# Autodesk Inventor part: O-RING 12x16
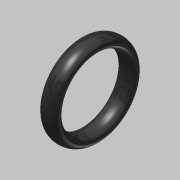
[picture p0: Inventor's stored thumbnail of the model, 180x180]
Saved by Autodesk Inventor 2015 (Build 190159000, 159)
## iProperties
Created: 2020-02
Part Number: O-RING 12x16
Material: 고무
Document SubType Name: Modeling
Designer: mduedu
Density: 1 g/cm^3
Appearance: 고무 - 검은색 - 버전 1.1
Author: mduedu
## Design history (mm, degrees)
sketch "스케치1"
  geometry: L1 (-2.24, 0)-(2.24, 0) reference; L2 (-1.6, 7)-(1.6, 7); L3 (0, 8)-(0, 6); 6 further points; 1 other entity
  constraints: 4 end point, 3 coincident, 2 midpoint, 1 horizontal, 1 vertical, 1 vertical alignment, 6 other
  dimensions: "d0" = 1.6 distance of point (1.6, 7) point (0, 7); "d2" = 12 diameter of point (0, 6) L1; "d3" = 16 diameter of point (0, 8) L1
revolve "회전1" sketch "스케치1" stored, may be unused: angle "d4" = 90 deg
node "솔리드1"
